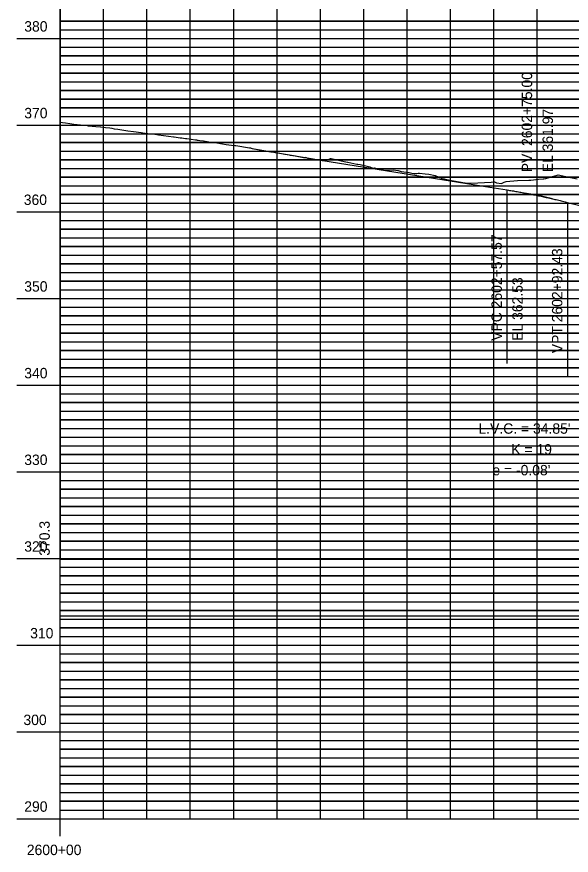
# Model space of a CAD drawing. Extents: x 1195880 to 1289360, y 2059330 to 2086925.
# Drawn here: x 1196975.1 to 1197294.7, y 2063753.6 to 2064237.3 of the extents above; entities that cross this region are included whole.
import ezdxf

# ---------------------------------------------------------------- set-up
doc = ezdxf.new("R2010")
doc.units = 0
for name, color, linetype in [('41', 7, 'Continuous'), ('51', 7, 'Continuous'), ('Clip', 7, 'Continuous'), ('Existing Ground PGL', 7, 'Continuous'), ('Grid', 7, 'Continuous'), ('Grid Lables', 7, 'Continuous'), ('Profile', 7, 'Continuous'), ('Profile Annotation', 7, 'Continuous')]:
    doc.layers.add(name, color=color, linetype=linetype)

msp = doc.modelspace()

# ---------------------------------------------------------------- linework, layer by layer
at = {"layer": 'Clip'}
msp.add_lwpolyline([(1197000.14, 2063924.39), (1197856.43, 2063924.39), (1197856.43, 2064284.72), (1197000.14, 2064284.72)], close=True, dxfattribs=at)
at = {"layer": 'Existing Ground PGL'}
msp.add_lwpolyline([(1197000.14, 2064176.45), (1197001.58, 2064176.24), (1197003.24, 2064175.99), (1197005.66, 2064175.64), (1197007.93, 2064175.37), (1197015.73, 2064174.46), (1197016.2, 2064174.41), (1197020.66, 2064173.89), (1197023.34, 2064173.73), (1197023.52, 2064173.71), (1197024.67, 2064173.64), (1197026.33, 2064173.44), (1197028.74, 2064173.14), (1197029.88, 2064172.95), (1197031.32, 2064172.71), (1197033.43, 2064172.36), (1197035.66, 2064171.98), (1197038, 2064171.69), (1197039.11, 2064171.54), (1197042.5, 2064171.09), (1197046.9, 2064170.52), (1197047.75, 2064170.41), (1197050.66, 2064170.02), (1197054.7, 2064169.47), (1197056.89, 2064169.18), (1197062.49, 2064168.43), (1197065.38, 2064168.05), (1197065.54, 2064168.03), (1197065.67, 2064168.01), (1197065.76, 2064168), (1197069.36, 2064167.51), (1197070.29, 2064167.38), (1197071.26, 2064167.25), (1197072.43, 2064167.1), (1197073.21, 2064166.99), (1197078.08, 2064166.33), (1197078.28, 2064166.3), (1197078.46, 2064166.27), (1197078.7, 2064166.24), (1197079.07, 2064166.18), (1197079.68, 2064166.08), (1197080.69, 2064165.92), (1197080.71, 2064165.91), (1197082.69, 2064165.62), (1197085.88, 2064165.15), (1197089.23, 2064164.65), (1197093.67, 2064163.97), (1197095.72, 2064163.66), (1197098.8, 2064163.28), (1197100.88, 2064163.02), (1197101.46, 2064162.93), (1197109.26, 2064161.74), (1197109.62, 2064161.68), (1197109.83, 2064161.6), (1197110.16, 2064161.46), (1197110.71, 2064161.24), (1197110.76, 2064161.23), (1197116.95, 2064160.19), (1197117.05, 2064160.18), (1197121.51, 2064159.43), (1197123.33, 2064159.13), (1197124.85, 2064158.87), (1197125.81, 2064158.71), (1197129.54, 2064158.04), (1197132.13, 2064157.58), (1197132.64, 2064157.49), (1197135.5, 2064156.98), (1197140.44, 2064156.1), (1197140.88, 2064156.02), (1197141.46, 2064156.15), (1197141.61, 2064156.2), (1197142.67, 2064155.75), (1197148.23, 2064154.86), (1197151.15, 2064154.4), (1197151.48, 2064154.34), (1197155.08, 2064155.2), (1197156.02, 2064155.46), (1197156.28, 2064155.54), (1197163.82, 2064153.82), (1197164.71, 2064153.62), (1197165.83, 2064153.33), (1197165.87, 2064153.32), (1197165.92, 2064153.32), (1197171.2, 2064152.32), (1197171.61, 2064152.28), (1197173.04, 2064152.13), (1197177.12, 2064151.01), (1197178.61, 2064150.64), (1197179.41, 2064150.41), (1197180.85, 2064150), (1197181.32, 2064150.18), (1197187.2, 2064148.87), (1197187.9, 2064148.72), (1197192.22, 2064148.88), (1197194.75, 2064148.58), (1197194.99, 2064148.5), (1197196.65, 2064148.01), (1197201.2, 2064147.52), (1197202.79, 2064147.08), (1197203.9, 2064146.78), (1197205.75, 2064146.77), (1197206.39, 2064147.02), (1197207.15, 2064147.04), (1197210.41, 2064146.66), (1197212.69, 2064146.39), (1197216.26, 2064145.68), (1197218.03, 2064144.92), (1197220.58, 2064143.81), (1197221.4, 2064143.77), (1197222.11, 2064143.58), (1197222.91, 2064143.42), (1197225.65, 2064142.88), (1197226.79, 2064142.65), (1197233.27, 2064141.4), (1197233.9, 2064141.27), (1197234.08, 2064141.23), (1197234.12, 2064141.23), (1197240.88, 2064141.54), (1197248.5, 2064141.88), (1197250.51, 2064141.97), (1197250.82, 2064141.86), (1197251.59, 2064141.57), (1197254.51, 2064141.1), (1197256.12, 2064141.83), (1197257.17, 2064142.29), (1197263.73, 2064142.85), (1197263.74, 2064142.85), (1197270.29, 2064142.94), (1197271.36, 2064143.08), (1197275.82, 2064143.59), (1197278.41, 2064143.69), (1197278.98, 2064143.76), (1197280.08, 2064143.89), (1197286.6, 2064145.87), (1197287.24, 2064146.06), (1197294.22, 2064144.6), (1197298.02, 2064143.78)], dxfattribs=at)
at = {"layer": 'Grid'}
for p, q in [((1197000.14, 2063774.72), (1197000.14, 2064474.72)), ((1197025.14, 2063774.72), (1197025.14, 2064474.72)), ((1197050.14, 2063774.72), (1197050.14, 2064474.72)), ((1197075.14, 2063774.72), (1197075.14, 2064474.72)), ((1197100.14, 2063774.72), (1197100.14, 2064474.72)), ((1197125.14, 2063774.72), (1197125.14, 2064474.72)), ((1197150.14, 2063774.72), (1197150.14, 2064474.72)), ((1197175.14, 2063774.72), (1197175.14, 2064474.72)), ((1197200.14, 2063774.72), (1197200.14, 2064474.72)), ((1197225.14, 2063774.72), (1197225.14, 2064474.72)), ((1197250.14, 2063774.72), (1197250.14, 2064474.72)), ((1197275.14, 2063774.72), (1197275.14, 2064474.72)), ((1197000.14, 2064234.72), (1197003.14, 2064234.72)), ((1197000.14, 2064234.72), (1198000.14, 2064234.72)), ((1198000.14, 2064234.72), (1197000.14, 2064234.72)), ((1197000.14, 2064229.72), (1197003.14, 2064229.72)), ((1197000.14, 2064229.72), (1198000.14, 2064229.72)), ((1196975.14, 2064224.72), (1197000.14, 2064224.72)), ((1197000.14, 2064224.72), (1198000.14, 2064224.72)), ((1197000.14, 2064219.72), (1197003.14, 2064219.72)), ((1197000.14, 2064219.72), (1198000.14, 2064219.72)), ((1197000.14, 2064214.72), (1197003.14, 2064214.72)), ((1197000.14, 2064214.72), (1198000.14, 2064214.72)), ((1198000.14, 2064214.72), (1197000.14, 2064214.72)), ((1197000.14, 2064209.72), (1197003.14, 2064209.72)), ((1197000.14, 2064209.72), (1198000.14, 2064209.72)), ((1197000.14, 2064204.72), (1197003.14, 2064204.72)), ((1197000.14, 2064204.72), (1198000.14, 2064204.72)), ((1198000.14, 2064204.72), (1197000.14, 2064204.72)), ((1197000.14, 2064199.72), (1197003.14, 2064199.72)), ((1197000.14, 2064199.72), (1198000.14, 2064199.72)), ((1197000.14, 2064194.72), (1197003.14, 2064194.72)), ((1197000.14, 2064194.72), (1198000.14, 2064194.72)), ((1198000.14, 2064194.72), (1197000.14, 2064194.72)), ((1198000.14, 2064189.77), (1197000.14, 2064189.77)), ((1197000.14, 2064189.72), (1197003.14, 2064189.72)), ((1197000.14, 2064189.72), (1198000.14, 2064189.72)), ((1197000.14, 2064184.72), (1197003.14, 2064184.72)), ((1197000.14, 2064184.72), (1198000.14, 2064184.72)), ((1198000.14, 2064184.72), (1197000.14, 2064184.72)), ((1197000.14, 2064179.72), (1197003.14, 2064179.72)), ((1197000.14, 2064179.72), (1198000.14, 2064179.72)), ((1196975.14, 2064174.72), (1197000.14, 2064174.72)), ((1197000.14, 2064174.72), (1198000.14, 2064174.72)), ((1197000.14, 2064169.72), (1197003.14, 2064169.72)), ((1197000.14, 2064169.72), (1198000.14, 2064169.72)), ((1197000.14, 2064164.72), (1197003.14, 2064164.72)), ((1197000.14, 2064164.72), (1198000.14, 2064164.72)), ((1198000.14, 2064164.72), (1197000.14, 2064164.72)), ((1197000.14, 2064159.72), (1197003.14, 2064159.72)), ((1197000.14, 2064159.72), (1198000.14, 2064159.72)), ((1197000.14, 2064154.72), (1197003.14, 2064154.72)), ((1197000.14, 2064154.72), (1198000.14, 2064154.72)), ((1198000.14, 2064154.72), (1197000.14, 2064154.72)), ((1197000.14, 2064149.72), (1197003.14, 2064149.72)), ((1197000.14, 2064149.72), (1198000.14, 2064149.72)), ((1197000.14, 2064144.72), (1197003.14, 2064144.72)), ((1197000.14, 2064144.72), (1198000.14, 2064144.72)), ((1198000.14, 2064144.72), (1197000.14, 2064144.72)), ((1197000.14, 2064139.72), (1197003.14, 2064139.72)), ((1197000.14, 2064139.72), (1198000.14, 2064139.72)), ((1197000.14, 2064134.72), (1197003.14, 2064134.72)), ((1197000.14, 2064134.72), (1198000.14, 2064134.72)), ((1198000.14, 2064134.72), (1197000.14, 2064134.72)), ((1197000.14, 2064129.72), (1197003.14, 2064129.72)), ((1197000.14, 2064129.72), (1198000.14, 2064129.72)), ((1196975.14, 2064124.72), (1197000.14, 2064124.72)), ((1197000.14, 2064124.72), (1198000.14, 2064124.72)), ((1197000.14, 2064119.72), (1197003.14, 2064119.72)), ((1197000.14, 2064119.72), (1198000.14, 2064119.72)), ((1197000.14, 2064114.72), (1197003.14, 2064114.72)), ((1197000.14, 2064114.72), (1198000.14, 2064114.72)), ((1198000.14, 2064114.72), (1197000.14, 2064114.72)), ((1197000.14, 2064109.72), (1197003.14, 2064109.72)), ((1197000.14, 2064109.72), (1198000.14, 2064109.72)), ((1197000.14, 2064104.72), (1197003.14, 2064104.72)), ((1197000.14, 2064104.72), (1198000.14, 2064104.72)), ((1198000.14, 2064104.72), (1197000.14, 2064104.72)), ((1197000.14, 2064099.72), (1197003.14, 2064099.72)), ((1197000.14, 2064099.72), (1198000.14, 2064099.72)), ((1197000.14, 2064094.72), (1197003.14, 2064094.72)), ((1197000.14, 2064094.72), (1198000.14, 2064094.72)), ((1198000.14, 2064094.72), (1197000.14, 2064094.72)), ((1197000.14, 2064089.72), (1197003.14, 2064089.72)), ((1197000.14, 2064089.72), (1198000.14, 2064089.72)), ((1197000.14, 2064084.72), (1197003.14, 2064084.72)), ((1197000.14, 2064084.72), (1198000.14, 2064084.72)), ((1198000.14, 2064084.72), (1197000.14, 2064084.72)), ((1197000.14, 2064079.72), (1197003.14, 2064079.72)), ((1197000.14, 2064079.72), (1198000.14, 2064079.72)), ((1196975.14, 2064074.72), (1197000.14, 2064074.72)), ((1197000.14, 2064074.72), (1198000.14, 2064074.72)), ((1197000.14, 2064069.72), (1197003.14, 2064069.72)), ((1197000.14, 2064069.72), (1198000.14, 2064069.72)), ((1197000.14, 2064064.72), (1197003.14, 2064064.72)), ((1197000.14, 2064064.72), (1198000.14, 2064064.72)), ((1198000.14, 2064064.72), (1197000.14, 2064064.72)), ((1197000.14, 2064059.72), (1197003.14, 2064059.72)), ((1197000.14, 2064059.72), (1198000.14, 2064059.72)), ((1197000.14, 2064054.72), (1197003.14, 2064054.72)), ((1197000.14, 2064054.72), (1198000.14, 2064054.72)), ((1198000.14, 2064054.72), (1197000.14, 2064054.72)), ((1197000.14, 2064049.72), (1197003.14, 2064049.72)), ((1197000.14, 2064049.72), (1198000.14, 2064049.72)), ((1197000.14, 2064044.72), (1197003.14, 2064044.72)), ((1197000.14, 2064044.72), (1198000.14, 2064044.72)), ((1198000.14, 2064044.72), (1197000.14, 2064044.72)), ((1197000.14, 2064039.72), (1197003.14, 2064039.72)), ((1197000.14, 2064039.72), (1198000.14, 2064039.72)), ((1197000.14, 2064034.72), (1197003.14, 2064034.72)), ((1197000.14, 2064034.72), (1198000.14, 2064034.72)), ((1198000.14, 2064034.72), (1197000.14, 2064034.72)), ((1197000.14, 2064029.72), (1197003.14, 2064029.72)), ((1197000.14, 2064029.72), (1198000.14, 2064029.72)), ((1196975.14, 2064024.72), (1197000.14, 2064024.72)), ((1197000.14, 2064024.72), (1198000.14, 2064024.72)), ((1197000.14, 2064019.72), (1197003.14, 2064019.72)), ((1197000.14, 2064019.72), (1198000.14, 2064019.72)), ((1197000.14, 2064014.72), (1197003.14, 2064014.72)), ((1197000.14, 2064014.72), (1198000.14, 2064014.72)), ((1198000.14, 2064014.72), (1197000.14, 2064014.72)), ((1197000.14, 2064009.72), (1197003.14, 2064009.72)), ((1197000.14, 2064009.72), (1198000.14, 2064009.72)), ((1197000.14, 2064004.72), (1197003.14, 2064004.72)), ((1197000.14, 2064004.72), (1198000.14, 2064004.72)), ((1198000.14, 2064004.72), (1197000.14, 2064004.72)), ((1197000.14, 2063999.72), (1197003.14, 2063999.72)), ((1197000.14, 2063999.72), (1198000.14, 2063999.72)), ((1197000.14, 2063994.72), (1197003.14, 2063994.72)), ((1197000.14, 2063994.72), (1198000.14, 2063994.72)), ((1197000.14, 2063989.72), (1197003.14, 2063989.72)), ((1197000.14, 2063989.72), (1198000.14, 2063989.72)), ((1197000.14, 2063984.72), (1197003.14, 2063984.72)), ((1197000.14, 2063984.72), (1198000.14, 2063984.72)), ((1198000.14, 2063984.72), (1197000.14, 2063984.72)), ((1197000.14, 2063979.72), (1197003.14, 2063979.72)), ((1197000.14, 2063979.72), (1198000.14, 2063979.72)), ((1196975.14, 2063974.72), (1197000.14, 2063974.72)), ((1197000.14, 2063974.72), (1198000.14, 2063974.72)), ((1197000.14, 2063969.72), (1197003.14, 2063969.72)), ((1197000.14, 2063969.72), (1198000.14, 2063969.72)), ((1197000.14, 2063964.72), (1197003.14, 2063964.72)), ((1197000.14, 2063964.72), (1198000.14, 2063964.72)), ((1198000.14, 2063964.72), (1197000.14, 2063964.72)), ((1197000.14, 2063959.72), (1197003.14, 2063959.72)), ((1197000.14, 2063959.72), (1198000.14, 2063959.72)), ((1197000.14, 2063954.72), (1197003.14, 2063954.72)), ((1197000.14, 2063954.72), (1198000.14, 2063954.72)), ((1198000.14, 2063954.72), (1197000.14, 2063954.72)), ((1197000.14, 2063949.72), (1197003.14, 2063949.72)), ((1197000.14, 2063949.72), (1198000.14, 2063949.72)), ((1197000.14, 2063944.72), (1197003.14, 2063944.72)), ((1197000.14, 2063944.72), (1198000.14, 2063944.72)), ((1198000.14, 2063944.72), (1197000.14, 2063944.72)), ((1197000.14, 2063939.72), (1197003.14, 2063939.72)), ((1197000.14, 2063939.72), (1198000.14, 2063939.72)), ((1197000.14, 2063934.72), (1197003.14, 2063934.72)), ((1197000.14, 2063934.72), (1198000.14, 2063934.72)), ((1198000.14, 2063934.72), (1197000.14, 2063934.72)), ((1197000.14, 2063929.72), (1197003.14, 2063929.72)), ((1197000.14, 2063929.72), (1198000.14, 2063929.72)), ((1196975.14, 2063924.72), (1197000.14, 2063924.72)), ((1197000.14, 2063924.72), (1198000.14, 2063924.72)), ((1197000.14, 2063919.72), (1197003.14, 2063919.72)), ((1197000.14, 2063919.72), (1198000.14, 2063919.72)), ((1197000.14, 2063914.72), (1197003.14, 2063914.72)), ((1197000.14, 2063914.72), (1198000.14, 2063914.72)), ((1198000.14, 2063914.72), (1197000.14, 2063914.72)), ((1197000.14, 2063909.72), (1197003.14, 2063909.72)), ((1197000.14, 2063909.72), (1198000.14, 2063909.72)), ((1197000.14, 2063904.72), (1197003.14, 2063904.72)), ((1197000.14, 2063904.72), (1198000.14, 2063904.72)), ((1198000.14, 2063904.72), (1197000.14, 2063904.72)), ((1197000.14, 2063899.72), (1197003.14, 2063899.72)), ((1197000.14, 2063899.72), (1198000.14, 2063899.72)), ((1197000.14, 2063894.72), (1197003.14, 2063894.72)), ((1197000.14, 2063894.72), (1198000.14, 2063894.72)), ((1198000.14, 2063894.72), (1197000.14, 2063894.72)), ((1198000.14, 2063891.49), (1197000.14, 2063891.49)), ((1197000.14, 2063889.72), (1197003.14, 2063889.72)), ((1197000.14, 2063889.72), (1198000.14, 2063889.72)), ((1197000.14, 2063884.72), (1197003.14, 2063884.72)), ((1197000.14, 2063884.72), (1198000.14, 2063884.72)), ((1198000.14, 2063884.72), (1197000.14, 2063884.72)), ((1197000.14, 2063879.72), (1197003.14, 2063879.72)), ((1197000.14, 2063879.72), (1198000.14, 2063879.72)), ((1196975.14, 2063874.72), (1197000.14, 2063874.72)), ((1197000.14, 2063874.72), (1198000.14, 2063874.72)), ((1197000.14, 2063869.72), (1197003.14, 2063869.72)), ((1197000.14, 2063869.72), (1198000.14, 2063869.72)), ((1197000.14, 2063864.72), (1197003.14, 2063864.72)), ((1197000.14, 2063864.72), (1198000.14, 2063864.72)), ((1198000.14, 2063864.72), (1197000.14, 2063864.72)), ((1197000.14, 2063859.72), (1197003.14, 2063859.72)), ((1197000.14, 2063859.72), (1198000.14, 2063859.72)), ((1197000.14, 2063854.72), (1197003.14, 2063854.72)), ((1197000.14, 2063854.72), (1198000.14, 2063854.72)), ((1198000.14, 2063854.72), (1197000.14, 2063854.72)), ((1197000.14, 2063849.72), (1197003.14, 2063849.72)), ((1197000.14, 2063849.72), (1198000.14, 2063849.72)), ((1197000.14, 2063844.72), (1197003.14, 2063844.72)), ((1197000.14, 2063844.72), (1198000.14, 2063844.72)), ((1198000.14, 2063844.72), (1197000.14, 2063844.72)), ((1197000.14, 2063839.72), (1197003.14, 2063839.72)), ((1197000.14, 2063839.72), (1198000.14, 2063839.72)), ((1197000.14, 2063834.72), (1197003.14, 2063834.72)), ((1197000.14, 2063834.72), (1198000.14, 2063834.72)), ((1198000.14, 2063834.72), (1197000.14, 2063834.72)), ((1197000.14, 2063829.72), (1197003.14, 2063829.72)), ((1197000.14, 2063829.72), (1198000.14, 2063829.72)), ((1196975.14, 2063824.72), (1197000.14, 2063824.72)), ((1197000.14, 2063824.72), (1198000.14, 2063824.72)), ((1197000.14, 2063819.72), (1197003.14, 2063819.72)), ((1197000.14, 2063819.72), (1198000.14, 2063819.72)), ((1197000.14, 2063814.72), (1197003.14, 2063814.72)), ((1197000.14, 2063814.72), (1198000.14, 2063814.72)), ((1198000.14, 2063814.72), (1197000.14, 2063814.72)), ((1197000.14, 2063809.72), (1197003.14, 2063809.72)), ((1197000.14, 2063809.72), (1198000.14, 2063809.72)), ((1197000.14, 2063804.72), (1197003.14, 2063804.72)), ((1197000.14, 2063804.72), (1198000.14, 2063804.72)), ((1198000.14, 2063804.72), (1197000.14, 2063804.72)), ((1197000.14, 2063799.72), (1197003.14, 2063799.72)), ((1197000.14, 2063799.72), (1198000.14, 2063799.72)), ((1197000.14, 2063794.72), (1197003.14, 2063794.72)), ((1197000.14, 2063794.72), (1198000.14, 2063794.72)), ((1198000.14, 2063794.72), (1197000.14, 2063794.72)), ((1197000.14, 2063789.72), (1197003.14, 2063789.72)), ((1197000.14, 2063789.72), (1198000.14, 2063789.72)), ((1197000.14, 2063784.72), (1197003.14, 2063784.72)), ((1197000.14, 2063784.72), (1198000.14, 2063784.72)), ((1198000.14, 2063784.72), (1197000.14, 2063784.72)), ((1197000.14, 2063779.72), (1197003.14, 2063779.72)), ((1197000.14, 2063779.72), (1198000.14, 2063779.72)), ((1196975.14, 2063774.72), (1197000.14, 2063774.72)), ((1197000.14, 2063774.72), (1198000.14, 2063774.72)), ((1197000.14, 2063764.72), (1197000.14, 2063774.72)), ((1197025.14, 2063774.72), (1197025.14, 2063777.72)), ((1197050.14, 2063774.72), (1197050.14, 2063777.72)), ((1197075.14, 2063774.72), (1197075.14, 2063777.72)), ((1197100.14, 2063774.72), (1197100.14, 2063777.72)), ((1197125.14, 2063774.72), (1197125.14, 2063777.72)), ((1197150.14, 2063774.72), (1197150.14, 2063777.72)), ((1197175.14, 2063774.72), (1197175.14, 2063777.72)), ((1197200.14, 2063774.72), (1197200.14, 2063777.72)), ((1197225.14, 2063774.72), (1197225.14, 2063777.72)), ((1197250.14, 2063774.72), (1197250.14, 2063777.72)), ((1197275.14, 2063774.72), (1197275.14, 2063777.72))]:
    msp.add_line(p, q, dxfattribs=at)
at = {"layer": 'Profile'}
for p, q in [((1197110.76, 2064161.23), (1197151.48, 2064154.34)), ((1197151.48, 2064154.34), (1197247.83, 2064138.94)), ((1197247.83, 2064138.94), (1197257.71, 2064137.36)), ((1197292.57, 2064130.2), (1197380.45, 2064108.09))]:
    msp.add_line(p, q, dxfattribs=at)
msp.add_lwpolyline([(1197257.71, 2064137.36), (1197258.44, 2064137.25), (1197259.16, 2064137.13), (1197259.89, 2064137.01), (1197260.62, 2064136.89), (1197261.34, 2064136.77), (1197262.07, 2064136.64), (1197262.8, 2064136.52), (1197263.52, 2064136.39), (1197264.25, 2064136.26), (1197264.97, 2064136.13), (1197265.7, 2064136), (1197266.43, 2064135.87), (1197267.15, 2064135.74), (1197267.88, 2064135.6), (1197268.6, 2064135.47), (1197269.33, 2064135.33), (1197270.06, 2064135.19), (1197270.78, 2064135.05), (1197271.51, 2064134.91), (1197272.23, 2064134.77), (1197272.96, 2064134.62), (1197273.69, 2064134.48), (1197274.41, 2064134.33), (1197275.87, 2064134.03), (1197276.59, 2064133.88), (1197277.32, 2064133.73), (1197278.04, 2064133.57), (1197278.77, 2064133.42), (1197279.5, 2064133.26), (1197280.22, 2064133.1), (1197280.95, 2064132.94), (1197281.67, 2064132.78), (1197282.4, 2064132.62), (1197283.13, 2064132.45), (1197283.85, 2064132.29), (1197284.58, 2064132.12), (1197285.31, 2064131.95), (1197286.03, 2064131.78), (1197286.76, 2064131.61), (1197287.48, 2064131.44), (1197288.21, 2064131.27), (1197288.94, 2064131.09), (1197289.66, 2064130.92), (1197290.39, 2064130.74), (1197291.11, 2064130.56), (1197291.84, 2064130.38), (1197292.57, 2064130.2)], dxfattribs=at)
at = {"layer": 'Profile Annotation'}
for p, q in [((1197275.14, 2064134.58), (1197275.14, 2064234.58)), ((1197257.71, 2064037.36), (1197257.71, 2064137.36)), ((1197266.43, 2064135.97), (1197275.14, 2064134.58)), ((1197275.14, 2064134.58), (1197283.85, 2064132.39)), ((1197292.57, 2064130.2), (1197292.57, 2064030.2))]:
    msp.add_line(p, q, dxfattribs=at)

# ---------------------------------------------------------------- texts
at = {"layer": '41'}
msp.add_text('370.3', height=6, rotation=90, dxfattribs=at).set_placement((1196994.14, 2063926.39))
at = {"layer": '51'}
msp.add_text('-', height=0.0001, dxfattribs=at).set_placement((1197000.14, 2063774.72))
at = {"layer": 'Grid Lables'}
for s, p in [('380', (1196979.45, 2064228.72)), ('370', (1196979.45, 2064178.72)), ('360', (1196979.16, 2064128.72)), ('350', (1196979.45, 2064078.72)), ('340', (1196979.45, 2064028.72)), ('330', (1196979.45, 2063978.72)), ('320', (1196979.45, 2063928.72)), ('310', (1196982.85, 2063878.72)), ('300', (1196978.97, 2063828.72)), ('290', (1196979.45, 2063778.72)), ('2600+00', (1196980.93, 2063753.72))]:
    msp.add_text(s, height=6, dxfattribs=at).set_placement(p)
at = {"layer": 'Profile Annotation'}
for s, p in [('PVI 2602+75.00', (1197272.14, 2064147.58)), ('EL 361.97', (1197284.14, 2064147.58)), ('VPC 2602+57.57', (1197254.71, 2064050.36)), ('VPT 2602+92.43', (1197289.57, 2064043.2)), ('EL 362.53', (1197266.71, 2064050.36))]:
    msp.add_text(s, height=6, rotation=90, dxfattribs=at).set_placement(p)
for s, p in [("L.V.C. = 34.85'", (1197241.22, 2063996.75)), ('K = 19', (1197260.14, 2063984.75)), ("e = -0.08'", (1197249.25, 2063972.75))]:
    msp.add_text(s, height=6, dxfattribs=at).set_placement(p)

doc.saveas('drawing.dxf')
